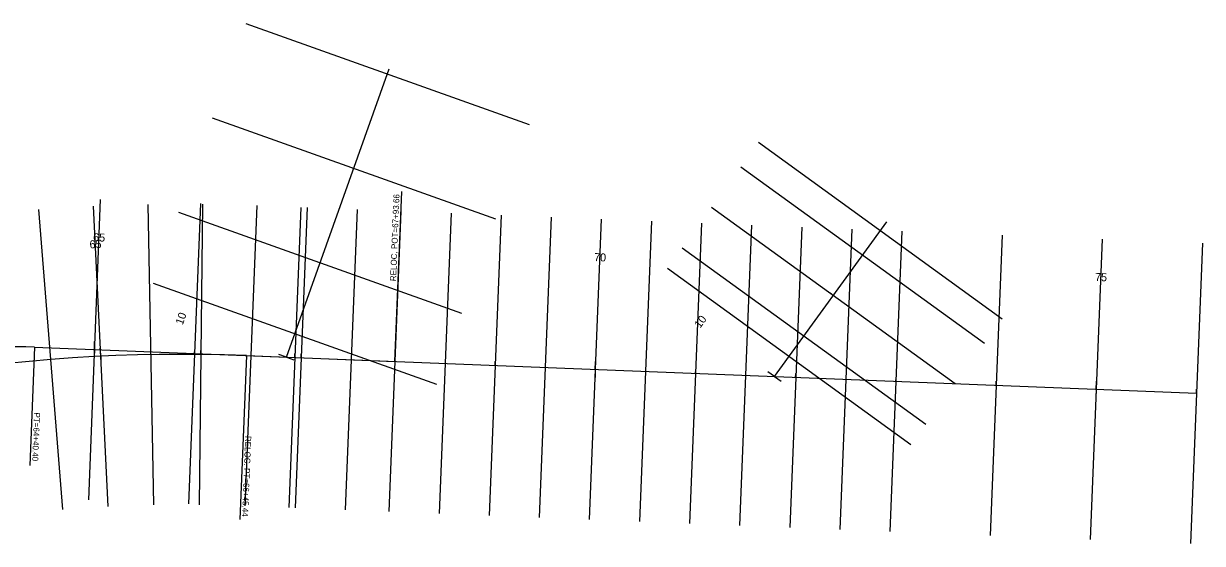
# Model space of a CAD drawing. Extents: x 1966723 to 1969285, y 1117318 to 1118467.
# Drawn here: x 1968109 to 1969285, y 1117735 to 1118254 of the extents above; entities that cross this region are included whole.
import ezdxf

# ---------------------------------------------------------------- set-up
doc = ezdxf.new("R2010")
doc.units = 0
for name, color, linetype in [('Level 1', 7, 'Continuous'), ('Level 19', 7, 'Continuous'), ('Level 21', 7, 'Continuous'), ('Level 39', 7, 'Continuous'), ('Level 50', 7, 'Continuous'), ('Level 51', 7, 'Continuous')]:
    doc.layers.add(name, color=color, linetype=linetype)

msp = doc.modelspace()

# ---------------------------------------------------------------- linework, layer by layer
at = {"layer": 'Level 1'}
for p, q in [((1968371.4, 1117921), (1968474, 1118208.6)), ((1968472.1, 1118203.5), (1968468.4, 1118204.9)), ((1968438.5, 1118109.4), (1968434.8, 1118110.7)), ((1968858.2, 1117901.7), (1968970.1, 1118056.2)), ((1968404.9, 1118015.2), (1968401.2, 1118016.5)), ((1968916.8, 1117982.6), (1968913.6, 1117985)), ((1968120.3, 1117930.9), (1968115.6, 1117812.9)), ((1968120.3, 1117930.9), (1969279, 1117884.9)), ((1968179.9, 1117928.6), (1968179.6, 1117920.6)), ((1968179.9, 1117928.6), (1968180.2, 1117936.6)), ((1968279.8, 1117924.6), (1968280, 1117928.6)), ((1968371.4, 1117921), (1968363.8, 1117923.7)), ((1968371.4, 1117921), (1968378.9, 1117918.3)), ((1968379.7, 1117920.6), (1968379.9, 1117924.6)), ((1968479.6, 1117916.7), (1968479.8, 1117920.7)), ((1968579.6, 1117912.7), (1968579.7, 1117916.7)), ((1968679.5, 1117908.7), (1968679.8, 1117916.7)), ((1968679.5, 1117908.7), (1968679.2, 1117900.8)), ((1968779.4, 1117904.8), (1968779.6, 1117908.8)), ((1968858.2, 1117901.7), (1968851.7, 1117906.3)), ((1968879.3, 1117900.8), (1968879.5, 1117904.8)), ((1968858.2, 1117901.7), (1968864.7, 1117897)), ((1968979.3, 1117896.8), (1968979.4, 1117900.8)), ((1969079.2, 1117892.9), (1969079.3, 1117896.9)), ((1969179.1, 1117888.9), (1969179.4, 1117896.9)), ((1969179.1, 1117888.9), (1969178.8, 1117880.9)), ((1969279, 1117884.9), (1969279.2, 1117888.9))]:
    msp.add_line(p, q, dxfattribs=at)
msp.add_arc((1968094.4, 1117277.5), 653.9, 87.7266, 111.9958, dxfattribs=at)
at = {"layer": 'Level 19'}
for p, q in [((1968186.2, 1117921.9), (1968185.8, 1117929.9)), ((1968286.1, 1117923.7), (1968286.2, 1117927.7)), ((1968186.2, 1117921.9), (1968186.5, 1117913.9)), ((1968331.5, 1117922.6), (1968479.6, 1117916.7)), ((1968386.1, 1117920.4), (1968386.2, 1117924.4))]:
    msp.add_line(p, q, dxfattribs=at)
msp.add_arc((1968266.6, 1116286.8), 1637, 87.7266, 111.9958, dxfattribs=at)
at = {"layer": 'Level 39'}
for p, q in [((1968479.6, 1117916.7), (1968486.4, 1118086.2)), ((1968331.5, 1117922.6), (1968325.1, 1117759.1))]:
    msp.add_line(p, q, dxfattribs=at)
at = {"layer": 'Level 50'}
for p, q in [((1968330.9, 1118253.9), (1968613.4, 1118153.2)), ((1968297.3, 1118159.7), (1968579.8, 1118059)), ((1968842.3, 1118135.4), (1969085.2, 1117959.4)), ((1968824.7, 1118111.1), (1969067.6, 1117935.1)), ((1968185.8, 1118078.5), (1968173.9, 1117778.7)), ((1968285.8, 1118074.5), (1968273.9, 1117774.7)), ((1968385.7, 1118070.5), (1968373.8, 1117770.8)), ((1968485.6, 1118066.6), (1968473.7, 1117766.8)), ((1968795.4, 1118070.6), (1969038.3, 1117894.6)), ((1968263.7, 1118065.6), (1968546.2, 1117964.8)), ((1968585.5, 1118062.6), (1968573.6, 1117762.8)), ((1968685.4, 1118058.6), (1968673.5, 1117758.9)), ((1968785.4, 1118054.7), (1968773.5, 1117754.9)), ((1968885.3, 1118050.7), (1968873.4, 1117750.9)), ((1968985.2, 1118046.7), (1968973.3, 1117747)), ((1969085.1, 1118042.8), (1969073.2, 1117743)), ((1969185, 1118038.8), (1969173.1, 1117739)), ((1969285, 1118034.8), (1969273.1, 1117735.1)), ((1968766, 1118030.1), (1969009, 1117854.1)), ((1968751.4, 1118009.9), (1968994.3, 1117833.9)), ((1968238.5, 1117994.9), (1968521, 1117894.1))]:
    msp.add_line(p, q, dxfattribs=at)
at = {"layer": 'Level 51'}
for p, q in [((1968124.3, 1118068.2), (1968148.2, 1117769.1)), ((1968178.8, 1118071.7), (1968193.5, 1117772.1)), ((1968233.3, 1118073.5), (1968238.9, 1117773.6)), ((1968287.9, 1118073.7), (1968284.3, 1117773.7)), ((1968342, 1118072.3), (1968330.1, 1117772.5)), ((1968392, 1118070.3), (1968380.1, 1117770.5)), ((1968442, 1118068.3), (1968430.1, 1117768.5)), ((1968485.6, 1118066.6), (1968473.7, 1117766.8)), ((1968535.6, 1118064.6), (1968523.7, 1117764.8)), ((1968585.5, 1118062.6), (1968573.6, 1117762.8)), ((1968635.5, 1118060.6), (1968623.6, 1117760.8)), ((1968685.4, 1118058.6), (1968673.5, 1117758.9)), ((1968735.4, 1118056.6), (1968723.5, 1117756.9)), ((1968785.4, 1118054.7), (1968773.5, 1117754.9)), ((1968835.3, 1118052.7), (1968823.4, 1117752.9)), ((1968885.3, 1118050.7), (1968873.4, 1117750.9)), ((1968935.2, 1118048.7), (1968923.3, 1117748.9)), ((1968985.2, 1118046.7), (1968973.3, 1117747))]:
    msp.add_line(p, q, dxfattribs=at)

# ---------------------------------------------------------------- texts
at = {"layer": 'Level 1'}
msp.add_text('PT=64+40.40', height=6, rotation=267.7266, dxfattribs=at).set_placement((1968119.8, 1117865.9))
at = {"layer": 'Level 19'}
msp.add_text('65', height=8, rotation=2.8169, dxfattribs=at).set_placement((1968175.3, 1118029.5))
at = {"layer": 'Level 21'}
for s, rotation, p in [('65', 357.7266, (1968178.6, 1118036.7)), ('70', 357.7266, (1968678.2, 1118016.9)), ('75', 357.7266, (1969177.8, 1117997.1)), ('10', 70.3698, (1968268, 1117952.6)), ('10', 54.0772, (1968784, 1117949.3))]:
    msp.add_text(s, height=8, rotation=rotation, dxfattribs=at).set_placement(p)
at = {"layer": 'Level 39'}
for s, rotation, p in [('RELOC. POT=67+93.66', 87.7266, (1968480.8, 1117996.7)), ('RELOC. PT=66+45.44', 267.7266, (1968330.4, 1117842.5))]:
    msp.add_text(s, height=6, rotation=rotation, dxfattribs=at).set_placement(p)

doc.saveas('drawing.dxf')
